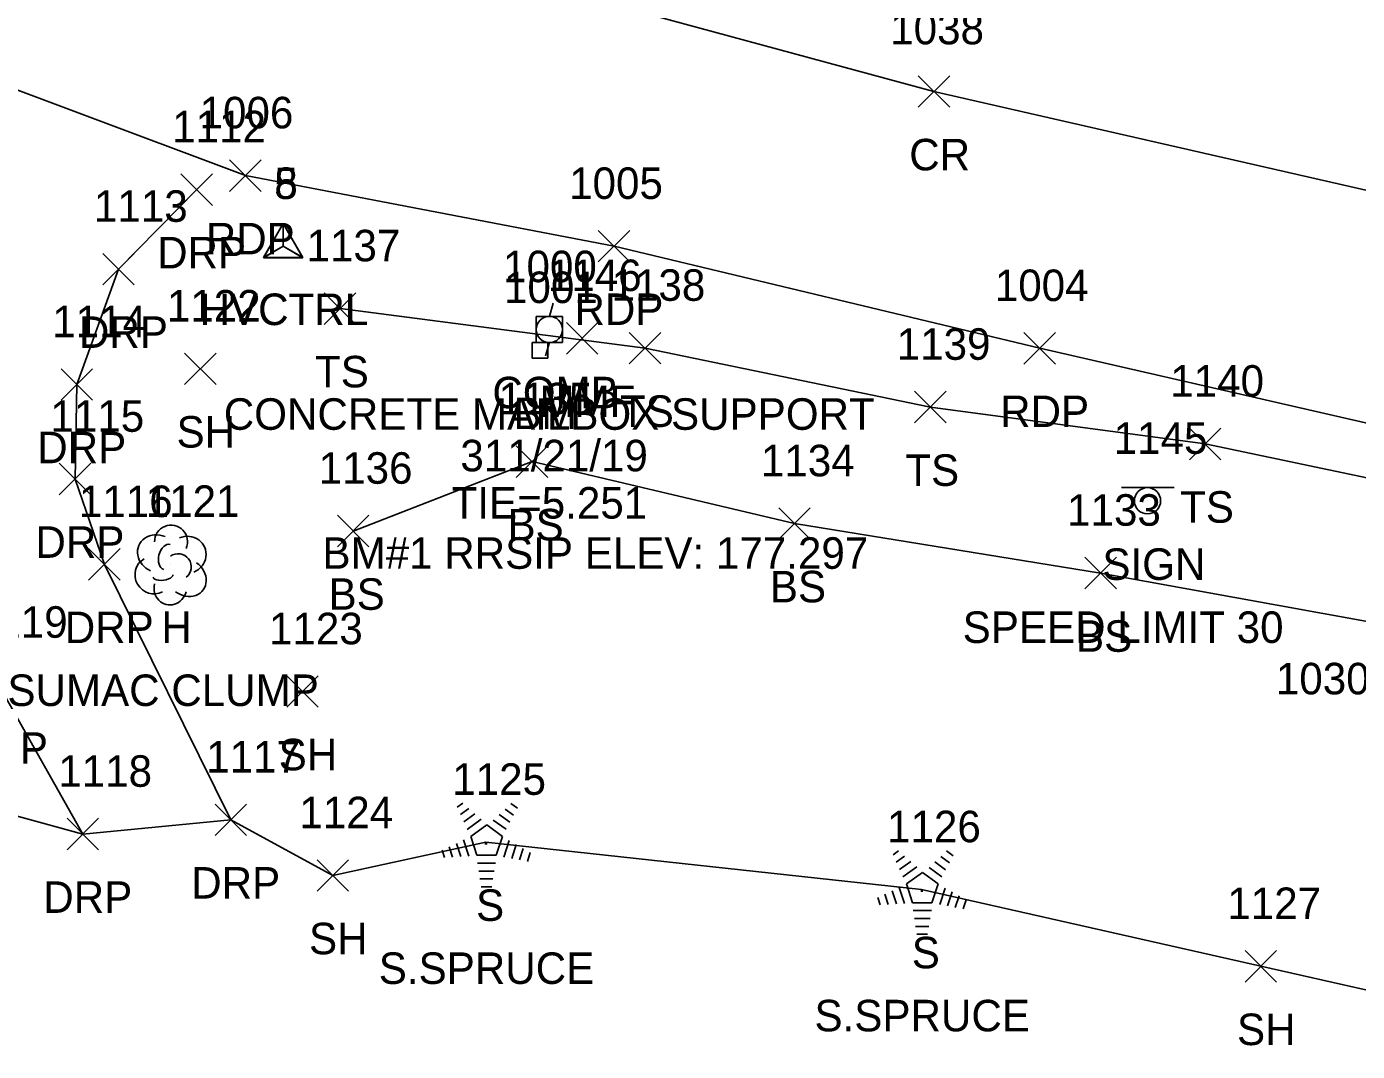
# Model space of a CAD drawing. Extents: x 1616726 to 1619875, y 273782 to 276557.
# Drawn here: x 1617199 to 1617283.4, y 276075.1 to 276140.1 of the extents above; entities that cross this region are included whole.
import ezdxf

# ---------------------------------------------------------------- set-up
doc = ezdxf.new("R2010")
doc.units = 0
for name, color, linetype in [('C_A', 7, 'Continuous'), ('C_C', 7, 'Continuous'), ('C_I', 7, 'Continuous'), ('CPBM', 7, 'Continuous'), ('CPSM', 7, 'Continuous'), ('L_A', 7, 'Continuous'), ('L_C', 7, 'Continuous'), ('L_I', 7, 'Continuous'), ('L_TIC', 7, 'Continuous'), ('LELB', 7, 'Continuous'), ('LSOGP', 7, 'Continuous'), ('LTC', 7, 'Continuous'), ('LTD', 7, 'Continuous'), ('P_A', 7, 'Continuous'), ('P_I', 7, 'Continuous'), ('P_TIC', 7, 'Continuous'), ('PET', 7, 'Continuous'), ('PRC', 7, 'Continuous'), ('R_A', 7, 'Continuous'), ('R_I', 7, 'Continuous'), ('R_TIC', 7, 'Continuous'), ('RDP', 7, 'Continuous'), ('S_A', 7, 'Continuous'), ('S_C', 7, 'Continuous'), ('S_I', 7, 'Continuous'), ('SSGN', 7, 'Continuous'), ('U_A', 7, 'Continuous'), ('U_C', 7, 'Continuous'), ('U_I', 7, 'Continuous'), ('UP', 7, 'Continuous')]:
    doc.layers.add(name, color=color, linetype=linetype)

msp = doc.modelspace()

# ---------------------------------------------------------------- linework, layer by layer
at = {"layer": 'CPBM'}
for p, q in [((1617231.053, 276119.062), (1617231.053, 276120.062)), ((1617231.053, 276120.062), (1617232.053, 276120.062)), ((1617232.053, 276120.062), (1617232.053, 276119.062)), ((1617232.053, 276119.062), (1617231.053, 276119.062)), ((1617231.556, 276119.563), (1617231.556, 276119.563)), ((1617231.556, 276119.563), (1617231.556, 276119.563))]:
    msp.add_line(p, q, dxfattribs=at)
at = {"layer": 'CPSM'}
for p, q in [((1617214.005, 276125.443), (1617215.255, 276127.608)), ((1617214.005, 276125.443), (1617215.255, 276127.608)), ((1617214.005, 276125.443), (1617215.255, 276127.608)), ((1617214.005, 276125.443), (1617215.255, 276127.608)), ((1617214.005, 276125.443), (1617215.255, 276127.608)), ((1617214.005, 276125.443), (1617215.255, 276127.608)), ((1617214.015, 276125.448), (1617215.265, 276127.613)), ((1617216.505, 276125.443), (1617215.255, 276127.608)), ((1617215.256, 276126.165), (1617215.255, 276127.608)), ((1617216.505, 276125.443), (1617215.255, 276127.608)), ((1617215.256, 276126.165), (1617215.255, 276127.608)), ((1617216.505, 276125.443), (1617215.255, 276127.608)), ((1617215.256, 276126.165), (1617215.255, 276127.608)), ((1617216.505, 276125.443), (1617215.255, 276127.608)), ((1617215.256, 276126.165), (1617215.255, 276127.608)), ((1617216.505, 276125.443), (1617215.255, 276127.608)), ((1617215.256, 276126.165), (1617215.255, 276127.608)), ((1617216.505, 276125.443), (1617215.255, 276127.608)), ((1617215.256, 276126.165), (1617215.255, 276127.608)), ((1617216.515, 276125.448), (1617215.265, 276127.613)), ((1617215.266, 276126.17), (1617215.265, 276127.613)), ((1617214.005, 276125.443), (1617215.256, 276126.165)), ((1617214.005, 276125.443), (1617215.256, 276126.165)), ((1617214.005, 276125.443), (1617215.256, 276126.165)), ((1617214.005, 276125.443), (1617215.256, 276126.165)), ((1617214.005, 276125.443), (1617215.256, 276126.165)), ((1617214.005, 276125.443), (1617215.256, 276126.165)), ((1617214.015, 276125.448), (1617215.266, 276126.17)), ((1617215.256, 276126.165), (1617215.256, 276126.165)), ((1617215.256, 276126.165), (1617216.505, 276125.443)), ((1617215.256, 276126.165), (1617215.256, 276126.165)), ((1617215.256, 276126.165), (1617216.505, 276125.443)), ((1617215.256, 276126.165), (1617215.256, 276126.165)), ((1617215.256, 276126.165), (1617216.505, 276125.443)), ((1617215.256, 276126.165), (1617215.256, 276126.165)), ((1617215.256, 276126.165), (1617216.505, 276125.443)), ((1617215.256, 276126.165), (1617215.256, 276126.165)), ((1617215.256, 276126.165), (1617216.505, 276125.443)), ((1617215.256, 276126.165), (1617215.256, 276126.165)), ((1617215.256, 276126.165), (1617216.505, 276125.443)), ((1617215.266, 276126.17), (1617215.266, 276126.17)), ((1617215.266, 276126.17), (1617216.515, 276125.448)), ((1617214.005, 276125.443), (1617216.505, 276125.443)), ((1617214.005, 276125.443), (1617216.505, 276125.443)), ((1617214.005, 276125.443), (1617216.505, 276125.443)), ((1617214.005, 276125.443), (1617216.505, 276125.443)), ((1617214.005, 276125.443), (1617216.505, 276125.443)), ((1617214.005, 276125.443), (1617216.505, 276125.443)), ((1617214.015, 276125.448), (1617216.515, 276125.448))]:
    msp.add_line(p, q, dxfattribs=at)
at = {"layer": 'L_TIC'}
for points in [[(1617217.869, 276121.211), (1617219.869, 276123.211)], [(1617219.869, 276121.211), (1617217.869, 276123.211)], [(1617233.237, 276119.324), (1617235.237, 276121.324)], [(1617235.237, 276119.324), (1617233.237, 276121.324)], [(1617237.224, 276118.705), (1617239.224, 276120.705)], [(1617239.224, 276118.705), (1617237.224, 276120.705)], [(1617209.005, 276117.391), (1617211.005, 276119.391)], [(1617211.005, 276117.391), (1617209.005, 276119.391)], [(1617255.329, 276114.962), (1617257.329, 276116.962)], [(1617257.329, 276114.962), (1617255.329, 276116.962)], [(1617272.766, 276112.623), (1617274.766, 276114.623)], [(1617274.766, 276112.623), (1617272.766, 276114.623)], [(1617230.053, 276111.501), (1617232.053, 276113.501)], [(1617232.053, 276111.501), (1617230.053, 276113.501)], [(1617218.698, 276107.096), (1617220.698, 276109.096)], [(1617220.698, 276107.096), (1617218.698, 276109.096)], [(1617246.703, 276107.569), (1617248.703, 276109.569)], [(1617248.703, 276107.569), (1617246.703, 276109.569)], [(1617266.132, 276104.432), (1617268.132, 276106.432)], [(1617268.132, 276104.432), (1617266.132, 276106.432)], [(1617215.486, 276096.91), (1617217.486, 276098.91)], [(1617217.486, 276096.91), (1617215.486, 276098.91)], [(1617217.412, 276085.237), (1617219.412, 276087.237)], [(1617219.412, 276085.237), (1617217.412, 276087.237)], [(1617276.301, 276079.472), (1617278.301, 276081.472)], [(1617278.301, 276079.472), (1617276.301, 276081.472)]]:
    msp.add_lwpolyline(points, dxfattribs=at)
at = {"layer": 'LELB'}
for points in [[(1617218.869, 276122.211), (1617238.224, 276119.705), (1617256.329, 276115.962), (1617273.766, 276113.623), (1617305.565, 276106.942), (1617343.23, 276099.015)], [(1617340.726, 276087.644), (1617319.571, 276092.598), (1617292.478, 276100.838), (1617267.132, 276105.432), (1617247.703, 276108.569), (1617231.053, 276112.501), (1617219.698, 276108.096)]]:
    msp.add_lwpolyline(points, dxfattribs=at)
at = {"layer": 'LSOGP'}
msp.add_lwpolyline([(1617140.035, 276109.296), (1617154.793, 276105.342), (1617179.88, 276096.126), (1617183.196, 276094.677), (1617185.748, 276094.71), (1617194.448, 276091.071), (1617202.547, 276088.865), (1617211.935, 276089.77), (1617218.412, 276086.237), (1617228.114, 276088.354), (1617255.764, 276085.345), (1617277.301, 276080.472), (1617301.293, 276075.073)], dxfattribs=at)
at = {"layer": 'LTC'}
for p, q in [((1617226.309, 276090.562), (1617226.663, 276090.819)), ((1617226.518, 276090.097), (1617227.048, 276090.481)), ((1617229.336, 276090.454), (1617229.885, 276090.055)), ((1617229.707, 276090.802), (1617230.126, 276090.498)), ((1617226.728, 276089.631), (1617227.432, 276090.142)), ((1617226.938, 276089.165), (1617227.816, 276089.803)), ((1617227.162, 276088.71), (1617228.174, 276089.444)), ((1617228.174, 276089.444), (1617229.171, 276088.719)), ((1617228.594, 276089.757), (1617229.403, 276089.169)), ((1617228.965, 276090.106), (1617229.644, 276089.612)), ((1617227.162, 276088.71), (1617227.549, 276087.517)), ((1617229.171, 276088.719), (1617228.78, 276087.517)), ((1617225.341, 276087.841), (1617225.493, 276087.373)), ((1617225.797, 276088.058), (1617226.008, 276087.406)), ((1617226.252, 276088.274), (1617226.523, 276087.439)), ((1617226.708, 276088.491), (1617227.038, 276087.472)), ((1617229.608, 276088.449), (1617229.27, 276087.409)), ((1617230.053, 276088.198), (1617229.765, 276087.314)), ((1617230.498, 276087.948), (1617230.26, 276087.219)), ((1617230.942, 276087.698), (1617230.755, 276087.124)), ((1617253.959, 276087.553), (1617254.314, 276087.81)), ((1617257.357, 276087.793), (1617257.776, 276087.489)), ((1617228.78, 276087.517), (1617227.549, 276087.517)), ((1617228.741, 276087.017), (1617227.597, 276087.017)), ((1617254.169, 276087.087), (1617254.698, 276087.472)), ((1617254.378, 276086.622), (1617255.082, 276087.133)), ((1617256.615, 276087.097), (1617257.294, 276086.603)), ((1617256.986, 276087.445), (1617257.536, 276087.046)), ((1617228.658, 276086.517), (1617227.669, 276086.517)), ((1617228.574, 276086.017), (1617227.742, 276086.017)), ((1617254.588, 276086.156), (1617255.466, 276086.794)), ((1617254.812, 276085.701), (1617255.824, 276086.435)), ((1617255.824, 276086.435), (1617256.821, 276085.71)), ((1617256.244, 276086.748), (1617257.054, 276086.159)), ((1617228.49, 276085.517), (1617227.815, 276085.517)), ((1617253.902, 276085.265), (1617254.174, 276084.43)), ((1617254.358, 276085.482), (1617254.689, 276084.462)), ((1617254.812, 276085.701), (1617255.199, 276084.507)), ((1617256.821, 276085.71), (1617256.43, 276084.507)), ((1617257.259, 276085.439), (1617256.921, 276084.4)), ((1617257.703, 276085.189), (1617257.416, 276084.304)), ((1617252.991, 276084.832), (1617253.144, 276084.364)), ((1617253.447, 276085.049), (1617253.659, 276084.397)), ((1617256.43, 276084.507), (1617255.199, 276084.507)), ((1617258.148, 276084.939), (1617257.911, 276084.209)), ((1617258.592, 276084.689), (1617258.405, 276084.114)), ((1617256.391, 276084.007), (1617255.247, 276084.007)), ((1617256.308, 276083.507), (1617255.319, 276083.507)), ((1617256.224, 276083.007), (1617255.392, 276083.007)), ((1617256.14, 276082.507), (1617255.465, 276082.507))]:
    msp.add_line(p, q, dxfattribs=at)
at = {"layer": 'LTD'}
msp.add_line((1617208.099, 276105.992), (1617208.099, 276105.992), dxfattribs=at)
msp.add_line((1617208.099, 276105.992), (1617208.099, 276105.992), dxfattribs=at)
msp.add_arc((1617208.145, 276107.426), 1.047, 335.52715, 180.95627, dxfattribs=at)
for centre, major_axis, ratio, start_param, end_param in [((1617207.307, 276106.659), (1.21, -0.512), 0.895232, 1.570796, 4.712389), ((1617207.89, 276106.451), (-0.208, -0.792), 0.645439, 3.141593, 6.283185), ((1617209.14, 276106.576), (-1.141, -0.483), 0.949671, 1.570796, 4.712389), ((1617207.015, 276105.284), (0.584, -1.042), 0.959034, 3.141593, 6.283185), ((1617208.599, 276105.826), (-0.5, 0.667), 0.989748, 3.141593, 6.283185), ((1617209.099, 276105.159), (-1.09, 0.792), 0.841452, 1.570796, 4.712389), ((1617208.099, 276104.492), (0.265, 1.061), 0.942809, 1.570796, 4.712389), ((1617207.64, 276105.242), (-0.625, -0.083), 0.423636, 0, 3.141593)]:
    msp.add_ellipse(centre, major_axis=major_axis, ratio=ratio, start_param=start_param, end_param=end_param, dxfattribs=at)
at = {"layer": 'P_TIC'}
for points in [[(1617255.555, 276134.984), (1617257.555, 276136.984)], [(1617257.555, 276134.984), (1617255.555, 276136.984)], [(1617211.86, 276129.651), (1617213.86, 276131.651)], [(1617213.86, 276129.651), (1617211.86, 276131.651)], [(1617235.256, 276125.171), (1617237.256, 276127.171)], [(1617237.256, 276125.171), (1617235.256, 276127.171)], [(1617262.27, 276118.69), (1617264.27, 276120.69)], [(1617264.27, 276118.69), (1617262.27, 276120.69)]]:
    msp.add_lwpolyline(points, dxfattribs=at)
at = {"layer": 'PET'}
msp.add_lwpolyline([(1617343.601, 276102.192), (1617300.74, 276111.108), (1617263.27, 276119.69), (1617236.256, 276126.171), (1617212.86, 276130.651), (1617190.893, 276138.889), (1617148.805, 276155.787), (1617124.366, 276159.729), (1617097.21, 276164.327), (1617058.671, 276171.511)], dxfattribs=at)
at = {"layer": 'PRC'}
msp.add_lwpolyline([(1617347.132, 276116.475), (1617295.92, 276126.996), (1617256.555, 276135.984), (1617216.872, 276146.76), (1617173.085, 276161.717), (1617139.463, 276175.956), (1617104.94, 276194.234), (1617079.375, 276210.711), (1617058.932, 276224.92), (1617047.068, 276234.028)], dxfattribs=at)
at = {"layer": 'R_TIC'}
for points in [[(1617208.774, 276128.764), (1617210.774, 276130.764)], [(1617210.774, 276128.764), (1617208.774, 276130.764)], [(1617203.81, 276123.718), (1617205.81, 276125.718)], [(1617205.81, 276123.718), (1617203.81, 276125.718)], [(1617201.166, 276116.398), (1617203.166, 276118.398)], [(1617203.166, 276116.398), (1617201.166, 276118.398)], [(1617201.049, 276110.394), (1617203.049, 276112.394)], [(1617203.049, 276110.394), (1617201.049, 276112.394)], [(1617202.91, 276104.981), (1617204.91, 276106.981)], [(1617204.91, 276104.981), (1617202.91, 276106.981)], [(1617210.935, 276088.77), (1617212.935, 276090.77)], [(1617212.935, 276088.77), (1617210.935, 276090.77)], [(1617201.547, 276087.865), (1617203.547, 276089.865)], [(1617203.547, 276087.865), (1617201.547, 276089.865)]]:
    msp.add_lwpolyline(points, dxfattribs=at)
at = {"layer": 'RDP'}
for points in [[(1617209.774, 276129.764), (1617204.81, 276124.718), (1617202.166, 276117.398), (1617202.049, 276111.394), (1617203.91, 276105.981), (1617211.935, 276089.77)], [(1617202.547, 276088.865), (1617197.199, 276098.323), (1617194.448, 276091.071)]]:
    msp.add_lwpolyline(points, dxfattribs=at)
at = {"layer": 'SSGN'}
for p, q in [((1617268.461, 276110.848), (1617271.794, 276110.848)), ((1617270.108, 276110.015), (1617270.108, 276110.015))]:
    msp.add_line(p, q, dxfattribs=at)
msp.add_circle((1617270.108, 276110.015), 0.833, dxfattribs=at)
at = {"layer": 'UP'}
for p, q in [((1617232.4, 276122.551), (1617232.15, 276121.718)), ((1617231.316, 276120.051), (1617231.316, 276121.718)), ((1617231.316, 276121.718), (1617232.983, 276121.718)), ((1617232.983, 276121.718), (1617232.983, 276120.051)), ((1617232.15, 276120.885), (1617232.15, 276120.885)), ((1617232.983, 276120.051), (1617231.316, 276120.051)), ((1617231.9, 276119.218), (1617232.15, 276120.051))]:
    msp.add_line(p, q, dxfattribs=at)
msp.add_circle((1617232.15, 276120.885), 0.833, dxfattribs=at)

# ---------------------------------------------------------------- texts
at = {"layer": 'C_A'}
for s, p in [('HVCTRL', (1617209.949, 276121.165)), ('HVCTRL', (1617209.949, 276121.165)), ('HVCTRL', (1617209.949, 276121.165)), ('HVCTRL', (1617209.949, 276121.165)), ('HVCTRL', (1617209.949, 276121.165)), ('HVCTRL', (1617209.949, 276121.165)), ('HVCTRL', (1617209.959, 276121.169)), ('BM', (1617229.871, 276114.563))]:
    msp.add_text(s, height=2, dxfattribs=at).set_placement(p)
at = {"layer": 'C_C'}
msp.add_text('BM#1 RRSIP ELEV: 177.297', height=2, dxfattribs=at).set_placement((1617217.751, 276105.699))
at = {"layer": 'C_I'}
for s, p in [('5', (1617214.689, 276129.165)), ('5', (1617214.689, 276129.165)), ('5', (1617214.689, 276129.165)), ('5', (1617214.689, 276129.165)), ('5', (1617214.689, 276129.165)), ('5', (1617214.689, 276129.165)), ('8', (1617214.699, 276129.17)), ('1001', (1617229.273, 276122.563))]:
    msp.add_text(s, height=2, dxfattribs=at).set_placement(p)
at = {"layer": 'L_A'}
for s, p in [('TS', (1617217.279, 276117.211)), ('MMF', (1617231.521, 276115.324)), ('TS', (1617236.633, 276114.705)), ('SH', (1617208.493, 276113.391)), ('TS', (1617254.739, 276110.962)), ('TS', (1617272.176, 276108.623)), ('BS', (1617229.494, 276107.501)), ('BS', (1617246.144, 276103.569)), ('BS', (1617218.139, 276103.096)), ('H', (1617207.532, 276100.992)), ('BS', (1617265.573, 276100.432)), ('SH', (1617214.975, 276092.91)), ('S', (1617227.499, 276083.354)), ('SH', (1617216.9, 276081.237)), ('S', (1617255.15, 276080.345)), ('SH', (1617275.789, 276075.472))]:
    msp.add_text(s, height=2, dxfattribs=at).set_placement(p)
at = {"layer": 'L_C'}
for s, p in [('CONCRETE MAILBOX SUPPORT', (1617211.49, 276114.52)), ('SUMAC CLUMP', (1617197.76, 276096.992)), ('S.SPRUCE', (1617221.326, 276079.354)), ('S.SPRUCE', (1617248.976, 276076.345))]:
    msp.add_text(s, height=2, dxfattribs=at).set_placement(p)
at = {"layer": 'L_I'}
for s, p in [('1137', (1617216.743, 276125.211)), ('1146', (1617232.056, 276123.324)), ('1138', (1617236.098, 276122.705)), ('1122', (1617207.879, 276121.391)), ('1139', (1617254.196, 276118.962)), ('1140', (1617271.554, 276116.623)), ('1135', (1617228.927, 276115.501)), ('1136', (1617217.517, 276111.096)), ('1134', (1617245.577, 276111.569)), ('1121', (1617206.539, 276108.992)), ('1133', (1617265.007, 276108.432)), ('1123', (1617214.36, 276100.91)), ('1125', (1617225.988, 276091.354)), ('1124', (1617216.286, 276089.237)), ('1126', (1617253.583, 276088.345)), ('1127', (1617275.175, 276083.472))]:
    msp.add_text(s, height=2, dxfattribs=at).set_placement(p)
at = {"layer": 'LTC'}
for p in [(1617228.056, 276088.458), (1617255.706, 276085.449)]:
    msp.add_text('.', height=1.037, rotation=270, dxfattribs=at).set_placement(p)
at = {"layer": 'P_A'}
for s, p in [('CR', (1617254.988, 276130.984)), ('RDP', (1617210.349, 276125.651)), ('RDP', (1617233.744, 276121.171)), ('RDP', (1617260.758, 276114.69))]:
    msp.add_text(s, height=2, dxfattribs=at).set_placement(p)
at = {"layer": 'P_I'}
for s, p in [('1038', (1617253.783, 276138.984)), ('1006', (1617209.955, 276133.651)), ('1005', (1617233.406, 276129.171)), ('1004', (1617260.42, 276122.69))]:
    msp.add_text(s, height=2, dxfattribs=at).set_placement(p)
at = {"layer": 'R_A'}
for p in [(1617207.262, 276124.764), (1617202.298, 276119.718), (1617199.654, 276112.398), (1617199.537, 276106.394), (1617201.399, 276100.981), (1617194.687, 276093.323), (1617209.423, 276084.77), (1617200.035, 276083.865)]:
    msp.add_text('DRP', height=2, dxfattribs=at).set_placement(p)
at = {"layer": 'R_I'}
for s, p in [('1112', (1617208.215, 276132.764)), ('1113', (1617203.251, 276127.718)), ('1114', (1617200.607, 276120.398)), ('1115', (1617200.49, 276114.394)), ('1116', (1617202.296, 276108.981)), ('1119', (1617195.632, 276101.323)), ('1117', (1617210.376, 276092.77)), ('1118', (1617200.988, 276091.865))]:
    msp.add_text(s, height=2, dxfattribs=at).set_placement(p)
at = {"layer": 'S_A'}
msp.add_text('SIGN', height=2, dxfattribs=at).set_placement((1617267.246, 276104.994))
at = {"layer": 'S_C'}
for s, p in [('SPEED LIMIT 30', (1617258.38, 276100.994)), ('1030/1407/0240', (1617278.255, 276097.731))]:
    msp.add_text(s, height=2, dxfattribs=at).set_placement(p)
at = {"layer": 'S_I'}
msp.add_text('1145', height=2, dxfattribs=at).set_placement((1617267.962, 276112.994))
at = {"layer": 'U_A'}
msp.add_text('COMB', height=2, dxfattribs=at).set_placement((1617228.535, 276115.885))
at = {"layer": 'U_C'}
for s, p in [('311/21/19', (1617226.504, 276111.885)), ('TIE=5.251', (1617225.945, 276108.885))]:
    msp.add_text(s, height=2, dxfattribs=at).set_placement(p)
at = {"layer": 'U_I'}
msp.add_text('1000', height=2, dxfattribs=at).set_placement((1617229.213, 276123.885))

doc.saveas('drawing.dxf')
